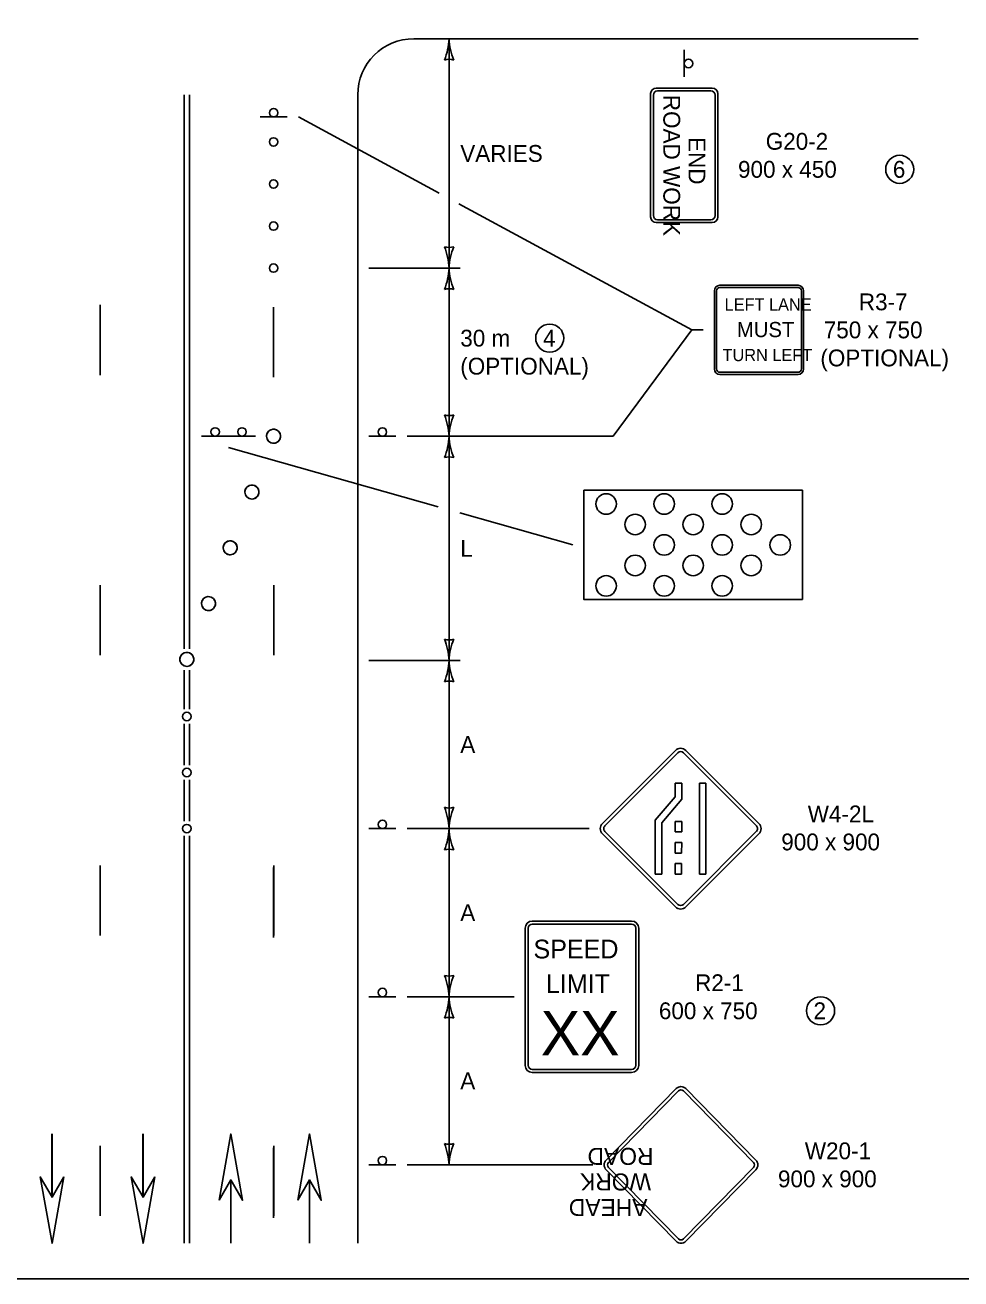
# Model space of a CAD drawing. Extents: x 49991.4 to 50021, y 49987.6 to 50011.4.
# Drawn here: x 50009.922 to 50013.262, y 49987.799 to 49992.273 of the extents above; entities that cross this region are included whole.
import ezdxf

# ---------------------------------------------------------------- set-up
doc = ezdxf.new("R2010")
doc.units = 0
for name, color, linetype in [('Level 1', 7, 'Continuous'), ('Level 2', 7, 'Continuous'), ('Level 3', 7, 'Continuous')]:
    doc.layers.add(name, color=color, linetype=linetype)

msp = doc.modelspace()

# ---------------------------------------------------------------- linework, layer by layer
at = {"layer": 'Level 1'}
for p, q in [((50013.109, 49992.224), (50011.309, 49992.224)), ((50012.2743, 49992.088), (50012.2743, 49992.184)), ((50012.1743, 49992.048), (50012.3743, 49992.048)), ((50012.1793, 49992.038), (50012.3693, 49992.038)), ((50010.489, 49990.0474), (50010.489, 49992.024)), ((50010.509, 49990.0474), (50010.509, 49992.024)), ((50011.109, 49987.9261), (50011.109, 49992.024)), ((50012.1543, 49991.5881), (50012.1543, 49992.0281)), ((50012.1643, 49991.593), (50012.1643, 49992.023)), ((50012.3843, 49991.593), (50012.3843, 49992.023)), ((50012.3943, 49991.588), (50012.3943, 49992.028)), ((50010.8571, 49991.945), (50010.7611, 49991.945)), ((50012.3743, 49991.568), (50012.1743, 49991.568)), ((50012.3693, 49991.578), (50012.1793, 49991.578)), ((50012.3818, 49991.0458), (50012.3818, 49991.3244)), ((50012.3898, 49991.0458), (50012.3898, 49991.3244)), ((50012.4017, 49991.3443), (50012.6804, 49991.3443)), ((50012.4017, 49991.3364), (50012.6804, 49991.3364)), ((50012.6923, 49991.3244), (50012.6923, 49991.0458)), ((50012.7003, 49991.3244), (50012.7003, 49991.0458)), ((50010.1892, 49991.024), (50010.1892, 49991.274)), ((50010.8087, 49991.0167), (50010.8087, 49991.2667)), ((50012.3818, 49991.0458), (50012.3818, 49991.0458)), ((50012.3898, 49991.0458), (50012.3898, 49991.0458)), ((50012.6804, 49991.0338), (50012.4017, 49991.0338)), ((50012.6804, 49991.0259), (50012.4017, 49991.0259)), ((50010.552, 49990.8057), (50010.648, 49990.8057)), ((50010.648, 49990.8057), (50010.744, 49990.8057)), ((50010.7939, 49990.8258), (50010.7939, 49990.8258)), ((50011.245, 49990.8057), (50011.149, 49990.8057)), ((50010.7165, 49990.6268), (50010.7165, 49990.6268)), ((50010.6391, 49990.4277), (50010.6391, 49990.4277)), ((50010.1892, 49990.024), (50010.1892, 49990.274)), ((50010.8092, 49990.024), (50010.8092, 49990.274)), ((50010.5617, 49990.2287), (50010.5617, 49990.2287)), ((50010.489, 49989.8318), (50010.489, 49989.9715)), ((50010.509, 49989.8318), (50010.509, 49989.9715)), ((50010.489, 49989.6318), (50010.489, 49989.7795)), ((50010.509, 49989.6318), (50010.509, 49989.7795)), ((50011.9821, 49989.4242), (50012.2427, 49989.6848)), ((50011.9909, 49989.4155), (50012.2514, 49989.6761)), ((50012.2713, 49989.6762), (50012.5317, 49989.4154)), ((50012.28, 49989.6849), (50012.5405, 49989.4242)), ((50010.489, 49989.4318), (50010.489, 49989.5795)), ((50010.509, 49989.4318), (50010.509, 49989.5795)), ((50012.2418, 49989.5194), (50012.2418, 49989.5679)), ((50012.2418, 49989.5679), (50012.2653, 49989.5679)), ((50012.2653, 49989.5679), (50012.2653, 49989.5108)), ((50012.3282, 49989.2436), (50012.3285, 49989.5679)), ((50012.3285, 49989.5679), (50012.3519, 49989.5678)), ((50012.3519, 49989.5678), (50012.3517, 49989.2436)), ((50012.1707, 49989.4355), (50012.2418, 49989.5194)), ((50012.2653, 49989.5108), (50012.1943, 49989.4264)), ((50011.245, 49989.4057), (50011.149, 49989.4057)), ((50012.2514, 49989.135), (50011.9908, 49989.3958)), ((50012.1707, 49989.2432), (50012.1707, 49989.4355)), ((50012.1943, 49989.4264), (50012.1942, 49989.2432)), ((50012.2417, 49989.3937), (50012.2417, 49989.4313)), ((50012.2417, 49989.4313), (50012.2652, 49989.4313)), ((50012.2652, 49989.4313), (50012.2652, 49989.3937)), ((50012.5318, 49989.3959), (50012.2712, 49989.1349)), ((50010.489, 49987.9261), (50010.489, 49989.3795)), ((50010.509, 49987.9261), (50010.509, 49989.3795)), ((50012.2426, 49989.1262), (50011.982, 49989.387)), ((50012.2652, 49989.3937), (50012.2417, 49989.3937)), ((50012.2417, 49989.3184), (50012.2417, 49989.356)), ((50012.2417, 49989.356), (50012.2652, 49989.356)), ((50012.2652, 49989.356), (50012.2651, 49989.3184)), ((50012.5406, 49989.3871), (50012.28, 49989.1261)), ((50012.2651, 49989.3184), (50012.2417, 49989.3184)), ((50010.1892, 49989.024), (50010.1892, 49989.274)), ((50010.1892, 49989.024), (50010.1892, 49989.274)), ((50010.8087, 49989.0167), (50010.8087, 49989.2667)), ((50010.8092, 49989.024), (50010.8092, 49989.274)), ((50010.8092, 49989.024), (50010.8092, 49989.274)), ((50012.2416, 49989.2431), (50012.2416, 49989.2808)), ((50012.2416, 49989.2808), (50012.2651, 49989.2808)), ((50012.2651, 49989.2808), (50012.2651, 49989.2431)), ((50012.1942, 49989.2432), (50012.1707, 49989.2432)), ((50012.2651, 49989.2431), (50012.2416, 49989.2431)), ((50012.3517, 49989.2436), (50012.3282, 49989.2436)), ((50011.7068, 49988.5609), (50011.7068, 49989.0504)), ((50011.7173, 49988.5609), (50011.7173, 49989.0504)), ((50011.7321, 49989.0757), (50012.0865, 49989.0757)), ((50011.7321, 49989.0651), (50012.0865, 49989.0651)), ((50011.9093, 49989.0757), (50011.9093, 49989.0757)), ((50012.1013, 49989.0504), (50012.1013, 49988.5609)), ((50012.1118, 49989.0504), (50012.1118, 49988.5609)), ((50011.245, 49988.8057), (50011.149, 49988.8057)), ((50012.0865, 49988.5462), (50011.7321, 49988.5462)), ((50012.0865, 49988.5356), (50011.7321, 49988.5356)), ((50011.9955, 49988.2228), (50012.2456, 49988.478)), ((50012.0038, 49988.2146), (50012.2539, 49988.4699)), ((50012.2714, 49988.4699), (50012.5215, 49988.2146)), ((50012.2798, 49988.478), (50012.5299, 49988.2228)), ((50010.0177, 49988.3162), (50010.0177, 49988.0903)), ((50010.0181, 49988.3162), (50010.0181, 49988.0903)), ((50010.3425, 49988.3162), (50010.3425, 49988.0903)), ((50010.3429, 49988.3162), (50010.3429, 49988.0903)), ((50010.1892, 49988.024), (50010.1892, 49988.274)), ((50010.1892, 49988.024), (50010.1892, 49988.274)), ((50010.8087, 49988.0167), (50010.8087, 49988.2667)), ((50010.8092, 49988.024), (50010.8092, 49988.274)), ((50010.8092, 49988.024), (50010.8092, 49988.274)), ((50011.245, 49988.2057), (50011.149, 49988.2057)), ((50012.2456, 49987.9334), (50011.9955, 49988.1886)), ((50012.2539, 49987.9415), (50012.0038, 49988.1968)), ((50012.5215, 49988.1968), (50012.2714, 49987.9415)), ((50012.5299, 49988.1886), (50012.2798, 49987.9334)), ((50010.656, 49987.9261), (50010.656, 49988.152)), ((50010.6564, 49987.9261), (50010.6564, 49988.152)), ((50010.937, 49987.9261), (50010.937, 49988.152)), ((50010.9374, 49987.9261), (50010.9374, 49988.152))]:
    msp.add_line(p, q, dxfattribs=at)
for points in [[(49999.3835, 49998.9992), (50016.7501, 49998.9992), (50016.7501, 49987.7988), (49999.3835, 49987.7988)], [(50012.6959, 49990.223), (50011.9162, 49990.223), (50011.9162, 49990.613), (50012.6959, 49990.613)], [(50012.6959, 49990.223), (50011.9162, 49990.223), (50011.9162, 49990.613), (50012.6959, 49990.613)], [(50010.6144, 49988.0797), (50010.656, 49988.3162), (50010.698, 49988.0797), (50010.656, 49988.1519)], [(50010.8954, 49988.0797), (50010.937, 49988.3162), (50010.979, 49988.0797), (50010.937, 49988.1519)], [(50010.0597, 49988.1626), (50010.0181, 49987.9261), (50009.9761, 49988.1626), (50010.0181, 49988.0904)], [(50010.3845, 49988.1626), (50010.3429, 49987.9261), (50010.3009, 49988.1626), (50010.3429, 49988.0904)]]:
    msp.add_lwpolyline(points, close=True, dxfattribs=at)
for centre, radius in [((50012.2895, 49992.136), 0.0152), ((50010.809, 49991.9602), 0.0152), ((50010.8087, 49991.8557), 0.015), ((50010.8087, 49991.7057), 0.015), ((50010.8087, 49991.5557), 0.015), ((50010.8087, 49991.4057), 0.015), ((50010.6, 49990.8209), 0.0152), ((50010.696, 49990.8209), 0.0152), ((50010.8087, 49990.8057), 0.025), ((50011.197, 49990.8208), 0.0152), ((50010.7313, 49990.6066), 0.025), ((50011.9956, 49990.564), 0.0366), ((50011.9956, 49990.564), 0.0366), ((50012.2027, 49990.564), 0.0366), ((50012.2027, 49990.564), 0.0366), ((50012.4098, 49990.564), 0.0366), ((50012.4098, 49990.564), 0.0366), ((50012.0991, 49990.4909), 0.0366), ((50012.0991, 49990.4909), 0.0366), ((50012.3062, 49990.4909), 0.0366), ((50012.3062, 49990.4909), 0.0366), ((50012.5134, 49990.4909), 0.0366), ((50012.5134, 49990.4909), 0.0366), ((50010.6538, 49990.4076), 0.025), ((50012.2027, 49990.4178), 0.0366), ((50012.2027, 49990.4178), 0.0366), ((50012.4098, 49990.4178), 0.0366), ((50012.4098, 49990.4178), 0.0366), ((50012.6169, 49990.4178), 0.0366), ((50012.6169, 49990.4178), 0.0366), ((50012.0991, 49990.3447), 0.0366), ((50012.0991, 49990.3447), 0.0366), ((50012.3062, 49990.3447), 0.0366), ((50012.3062, 49990.3447), 0.0366), ((50012.5134, 49990.3447), 0.0366), ((50012.5134, 49990.3447), 0.0366), ((50011.9956, 49990.2716), 0.0366), ((50011.9956, 49990.2716), 0.0366), ((50012.2027, 49990.2716), 0.0366), ((50012.2027, 49990.2716), 0.0366), ((50012.4098, 49990.2716), 0.0366), ((50012.4098, 49990.2716), 0.0366), ((50010.5764, 49990.2085), 0.025), ((50010.499, 49990.0095), 0.025), ((50010.499, 49989.8057), 0.015), ((50010.499, 49989.6057), 0.015), ((50010.499, 49989.4057), 0.015), ((50011.197, 49989.4208), 0.0152), ((50011.197, 49988.8208), 0.0152), ((50011.197, 49988.2208), 0.0152)]:
    msp.add_circle(centre, radius, dxfattribs=at)
for centre, radius, start, end in [((50011.309, 49992.024), 0.2, 90, 180), ((50012.1743, 49992.0281), 0.02, 90, 180), ((50012.1793, 49992.023), 0.015, 90, 180), ((50012.3693, 49992.023), 0.015, 360, 90), ((50012.3743, 49992.028), 0.02, 360, 90), ((50012.1743, 49991.5881), 0.02, 180, 270), ((50012.1793, 49991.593), 0.015, 180, 270), ((50012.3693, 49991.593), 0.015, 270, 360), ((50012.3743, 49991.588), 0.02, 270, 360), ((50012.4017, 49991.3244), 0.0199, 90, 180), ((50012.4017, 49991.3244), 0.0119, 90, 180), ((50012.6804, 49991.3244), 0.0199, 0, 90), ((50012.6804, 49991.3244), 0.0119, 0, 90), ((50012.4017, 49991.0458), 0.0199, 180, 270), ((50012.4017, 49991.0458), 0.0119, 180, 270), ((50012.6804, 49991.0458), 0.0119, 270, 0), ((50012.6804, 49991.0458), 0.0199, 270, 0), ((50010.8087, 49990.8057), 0.025, 306.2526, 126.2526), ((50010.8087, 49990.8057), 0.025, 126.2526, 306.2526), ((50010.7313, 49990.6066), 0.025, 126.2526, 306.2526), ((50010.7313, 49990.6066), 0.025, 306.2526, 126.2526), ((50010.6538, 49990.4076), 0.025, 126.2526, 306.2526), ((50010.6538, 49990.4076), 0.025, 306.2526, 126.2526), ((50010.5764, 49990.2085), 0.025, 126.2526, 306.2526), ((50010.5764, 49990.2085), 0.025, 306.2526, 126.2526), ((50010.499, 49990.0095), 0.025, 126.2526, 306.2526), ((50010.499, 49990.0095), 0.025, 306.2526, 126.2526), ((50012.2612, 49989.6662), 0.0263, 45.0001, 134.9999), ((50012.2614, 49989.6663), 0.0139, 45.0001, 134.9999), ((50012.0007, 49989.4057), 0.0263, 134.9999, 225.0001), ((50012.0007, 49989.4057), 0.0139, 134.9999, 225.0001), ((50012.5221, 49989.4057), 0.0139, 314.9999, 45.0001), ((50012.5221, 49989.4057), 0.0263, 314.9999, 45.0001), ((50012.2614, 49989.145), 0.0263, 225.0001, 314.9999), ((50012.2614, 49989.145), 0.0139, 225.0001, 314.9999), ((50011.7321, 49989.0504), 0.0253, 90, 180), ((50011.7321, 49989.0504), 0.0148, 90, 180), ((50012.0865, 49989.0504), 0.0253, 0, 90), ((50012.0865, 49989.0504), 0.0148, 0, 90), ((50011.7321, 49988.5609), 0.0253, 180, 270), ((50011.7321, 49988.5609), 0.0148, 180, 270), ((50012.0865, 49988.5609), 0.0148, 270, 360), ((50012.0865, 49988.5609), 0.0253, 270, 360)]:
    msp.add_arc(centre, radius, start, end, dxfattribs=at)
for centre, major_axis, ratio, start_param, end_param in [((50012.2627, 49988.4609), (0, 0.0243), 0.98963, 5.497787, 7.068583), ((50012.2627, 49988.4609), (0, 0.0126), 0.98, 5.497787, 7.068583), ((50012.0126, 49988.2057), (0, 0.0243), 0.98963, 0.785394, 2.356194), ((50012.0126, 49988.2057), (0, 0.0126), 0.98, 0.785394, 2.356194), ((50012.5128, 49988.2057), (0, 0.0126), 0.98, 3.926991, 5.497787), ((50012.5128, 49988.2057), (0, 0.0243), 0.98963, 3.926991, 5.497787), ((50012.2627, 49987.9504), (0, -0.0243), 0.98963, 5.497795, 7.068583), ((50012.2627, 49987.9504), (0, -0.0126), 0.98, 5.497795, 7.068583)]:
    msp.add_ellipse(centre, major_axis=major_axis, ratio=ratio, start_param=start_param, end_param=end_param, dxfattribs=at)
at = {"layer": 'Level 2'}
for centre in [(50013.0433, 49991.758), (50011.7942, 49991.1557), (50012.7609, 49988.7556)]:
    msp.add_circle(centre, 0.0501, dxfattribs=at)
at = {"layer": 'Level 3'}
for p, q in [((50011.435, 49991.4057), (50011.435, 49992.224)), ((50011.3998, 49991.6731), (50010.8971, 49991.945)), ((50012.3018, 49991.1851), (50011.4702, 49991.635)), ((50011.149, 49991.4057), (50011.475, 49991.4057)), ((50011.435, 49990.8057), (50011.435, 49991.4057)), ((50012.3018, 49991.1851), (50012.0203, 49990.8057)), ((50012.3418, 49991.1851), (50012.3018, 49991.1851)), ((50011.285, 49990.8057), (50012.0203, 49990.8057)), ((50011.435, 49990.0057), (50011.435, 49990.8057)), ((50011.3965, 49990.5538), (50010.648, 49990.7657)), ((50011.8762, 49990.418), (50011.4735, 49990.532)), ((50011.149, 49990.0057), (50011.475, 49990.0057)), ((50011.435, 49989.4057), (50011.435, 49990.0057)), ((50011.285, 49989.4057), (50011.9344, 49989.4057)), ((50011.435, 49988.8057), (50011.435, 49989.4057)), ((50011.6668, 49988.8057), (50011.285, 49988.8057)), ((50011.435, 49988.2057), (50011.435, 49988.8057)), ((50011.9485, 49988.2057), (50011.285, 49988.2057))]:
    msp.add_line(p, q, dxfattribs=at)
for centre, radius, start, end in [((50011.2129, 49992.2331), 0.2223, 337.456, 357.6395), ((50011.6677, 49992.2355), 0.233, 182.8273, 202.0772), ((50011.435, 49992.0958), 0.0548, 72.1388, 107.8612), ((50011.435, 49991.5339), 0.0548, 252.1388, 287.8612), ((50011.2023, 49991.3942), 0.233, 2.8273, 22.0772), ((50011.6572, 49991.3965), 0.2223, 157.456, 177.6395), ((50011.2129, 49991.4148), 0.2223, 337.456, 357.6395), ((50011.6677, 49991.4171), 0.233, 182.8273, 202.0772), ((50011.435, 49991.2774), 0.0548, 72.1388, 107.8612), ((50011.435, 49990.9339), 0.0548, 252.1388, 287.8612), ((50011.2023, 49990.7942), 0.233, 2.8273, 22.0772), ((50011.6572, 49990.7965), 0.2223, 157.456, 177.6395), ((50011.2129, 49990.8148), 0.2223, 337.456, 357.6395), ((50011.6677, 49990.8171), 0.233, 182.8273, 202.0772), ((50011.435, 49990.6774), 0.0548, 72.1388, 107.8612), ((50011.435, 49990.1339), 0.0548, 252.1388, 287.8612), ((50011.2023, 49989.9942), 0.233, 2.8273, 22.0772), ((50011.6572, 49989.9965), 0.2223, 157.456, 177.6395), ((50011.2129, 49990.0148), 0.2223, 337.456, 357.6395), ((50011.6677, 49990.0171), 0.233, 182.8273, 202.0772), ((50011.435, 49989.8774), 0.0548, 72.1388, 107.8612), ((50011.435, 49989.5339), 0.0548, 252.1388, 287.8612), ((50011.2023, 49989.3942), 0.233, 2.8273, 22.0772), ((50011.6572, 49989.3965), 0.2223, 157.456, 177.6395), ((50011.2129, 49989.4148), 0.2223, 337.456, 357.6395), ((50011.6677, 49989.4171), 0.233, 182.8273, 202.0772), ((50011.435, 49989.2774), 0.0548, 72.1388, 107.8612), ((50011.435, 49988.9339), 0.0548, 252.1388, 287.8612), ((50011.2023, 49988.7942), 0.233, 2.8273, 22.0772), ((50011.6572, 49988.7965), 0.2223, 157.456, 177.6395), ((50011.2129, 49988.8148), 0.2223, 337.456, 357.6395), ((50011.6677, 49988.8171), 0.233, 182.8273, 202.0772), ((50011.435, 49988.6774), 0.0548, 72.1388, 107.8612), ((50011.435, 49988.3339), 0.0548, 252.1388, 287.8612), ((50011.2023, 49988.1942), 0.233, 2.8273, 22.0772), ((50011.6572, 49988.1965), 0.2223, 157.456, 177.6395)]:
    msp.add_arc(centre, radius, start, end, dxfattribs=at)

# ---------------------------------------------------------------- texts
at = {"layer": 'Level 1'}
for s, height, rotation, p in [('ROAD WORK', 0.06, 270, (50012.1997, 49992.0239)), ('END', 0.06, 270, (50012.2897, 49991.8732)), ('ROAD', 0.06086, 180, (50012.1644, 49988.2665)), ('WORK', 0.06086, 180, (50012.1559, 49988.1753)), ('AHEAD', 0.06086, 180, (50012.1429, 49988.084))]:
    msp.add_text(s, height=height, rotation=rotation, dxfattribs=at).set_placement(p)
for s, height, p in [('LEFT LANE', 0.04352, (50012.4183, 49991.2541)), ('MUST', 0.05413, (50012.4621, 49991.1593)), ('TURN LEFT', 0.04352, (50012.411, 49991.0737)), ('SPEED', 0.06695, (50011.7362, 49988.9424)), ('LIMIT', 0.06695, (50011.7805, 49988.8187)), ('XX', 0.15772, (50011.7622, 49988.5967))]:
    msp.add_text(s, height=height, dxfattribs=at).set_placement(p)
at = {"layer": 'Level 2'}
for s, p in [('G20-2', (50012.5651, 49991.828)), ('VARIES', (50011.475, 49991.7848)), ('900 x 450', (50012.4663, 49991.728)), ('6', (50013.0188, 49991.728)), ('R3-7', (50012.8974, 49991.2551)), ('30 m', (50011.475, 49991.1257)), ('4', (50011.7703, 49991.1257)), ('750 x 750', (50012.7723, 49991.1551)), ('(OPTIONAL)', (50012.7601, 49991.0551)), ('(OPTIONAL)', (50011.475, 49991.0257)), ('L', (50011.475, 49990.3757)), ('W4-2L', (50012.7151, 49989.428)), ('900 x 900', (50012.6206, 49989.328)), ('R2-1', (50012.313, 49988.8256)), ('600 x 750', (50012.1838, 49988.7256)), ('2', (50012.7357, 49988.7256)), ('W20-1', (50012.7047, 49988.2258)), ('900 x 900', (50012.6088, 49988.1258))]:
    msp.add_text(s, height=0.06, dxfattribs=at).set_placement(p)
for p in [(50011.475, 49989.6757), (50011.475, 49989.0757), (50011.475, 49988.4757)]:
    msp.add_text('A', height=0.06, rotation=360, dxfattribs=at).set_placement(p)

doc.saveas('drawing.dxf')
